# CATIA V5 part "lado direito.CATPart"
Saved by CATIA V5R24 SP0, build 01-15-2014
Part number: lado direito
Bounding box of the stored display mesh (mm): x 0 to 3, y -198.5 to 198.5, z -225 to 225
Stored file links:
  C:\Users\Fatec\Desktop\Maquina componentes catia\lado direito.CATPart
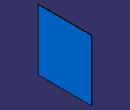
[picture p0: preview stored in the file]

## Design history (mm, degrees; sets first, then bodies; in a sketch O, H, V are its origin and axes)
Body1 (main body)
  Sketch1 on yz-plane, origin (0, 0, 0), H (0, 1, 0), V (0, 0, 1)
    line L1 (-198.5, 225) -> (198.5, 225)
    line L2 (198.5, 225) -> (198.5, -225)
    line L3 (198.5, -225) -> (-198.5, -225)
    line L4 (-198.5, -225) -> (-198.5, 225)
    length L3 = 397
    length L4 = 450
    horizontal: L1 H, L3 H
    vertical: L2 V, L4 V
    symmetry: L4 L2 V, L3 L1 H
  Pad1: profile Sketch1, direction (1, 0, 0), length 3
